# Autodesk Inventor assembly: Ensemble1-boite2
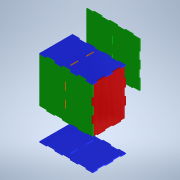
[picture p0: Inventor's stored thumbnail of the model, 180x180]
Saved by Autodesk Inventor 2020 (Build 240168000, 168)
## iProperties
Created: 2023-12
Part Number: Ensemble1-boite2
Document SubType Name: Assembly
Designer: bruno
Author: bruno
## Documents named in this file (7)
- C:\Users\bruno\Documents\1-Cours-2023-24\1STI2D\IT\Escape-game\Inventor_uhl\Boite2\Ensemble1-boite2.iam
- C:\Users\bruno\Documents\1-Cours-2023-24\1STI2D\IT\Escape-game\Inventor_uhl\Boite2\Grd-cote.ipt
- C:\Users\bruno\Documents\1-Cours-2023-24\1STI2D\IT\Escape-game\Inventor_uhl\Boite2\Ptit-cote.ipt
- C:\Users\bruno\Documents\1-Cours-2023-24\1STI2D\IT\Escape-game\Inventor_uhl\Boite2\Fond.ipt
- C:\Users\bruno\Documents\1-Cours-2023-24\1STI2D\IT\Escape-game\Inventor_uhl\Boite2\milieu.ipt
- C:\Users\bruno\Documents\1-Cours-2023-24\1STI2D\IT\Escape-game\Inventor_uhl\Boite2\corps moto reducteur.ipt
- C:\Users\bruno\Documents\1-Cours-2023-24\1STI2D\IT\Escape-game\Inventor_uhl\Boite2\raspberry-pi-pico-w-rp2040-no-pins-pins-and-socketed-1.snapshot.5\Ensemble-raspberry.iam
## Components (8 placed, 6 different names)
1. Grd-cote:1 — Affleurement:1, Placage:1, Affleurement:2, Placage:2, Placage:4, Affleurement:9, Affleurement:10
2. Ptit-cote:1 — Affleurement:1, Placage:1, Affleurement:2, Affleurement:3, Affleurement:4, Affleurement:5, Affleurement:6, Placage:7, Angle:1
3. Fond:1 — Placage:2, Affleurement:3, Affleurement:4, Placage:3
4. milieu:1 — Placage:3, Placage:4, Affleurement:5, Logement:1
5. corps moto reducteur:1 — Logement:1
6. Grd-cote:2 — Affleurement:6
7. Ptit-cote:2 — Affleurement:9, Affleurement:10
8. Ensemble-raspberry:1 [sub-assembly] — Placage:7, Angle:1
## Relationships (15: Flush 8, Mate 5, Insert 1, Angle 1)
- Affleurement:1 [Flush]: Grd-cote:1 ↔ Ptit-cote:1
- Placage:1 [Mate]: Grd-cote:1 ↔ Ptit-cote:1
- Affleurement:2 [Flush]: Grd-cote:1 ↔ Ptit-cote:1
- Placage:2 [Mate]: Grd-cote:1 ↔ Fond:1
- Affleurement:3 [Flush]: Ptit-cote:1 ↔ Fond:1
- Affleurement:4 [Flush]: Ptit-cote:1 ↔ Fond:1
- Placage:3 [Mate]: Fond:1 ↔ milieu:1
- Placage:4 [Mate]: Grd-cote:1 ↔ milieu:1
- Affleurement:5 [Flush]: Ptit-cote:1 ↔ milieu:1
- Logement:1 [Insert]: milieu:1 ↔ corps moto reducteur:1
- Affleurement:6 [Flush]: Ptit-cote:1 ↔ Grd-cote:2
- Affleurement:9 [Flush]: Grd-cote:1 ↔ Ptit-cote:2
- Affleurement:10 [Flush]: Grd-cote:1 ↔ Ptit-cote:2
- Placage:7 [Mate]: Ptit-cote:1 ↔ Ensemble-raspberry:1
- Angle:1: Ptit-cote:1 ↔ Ensemble-raspberry:1
